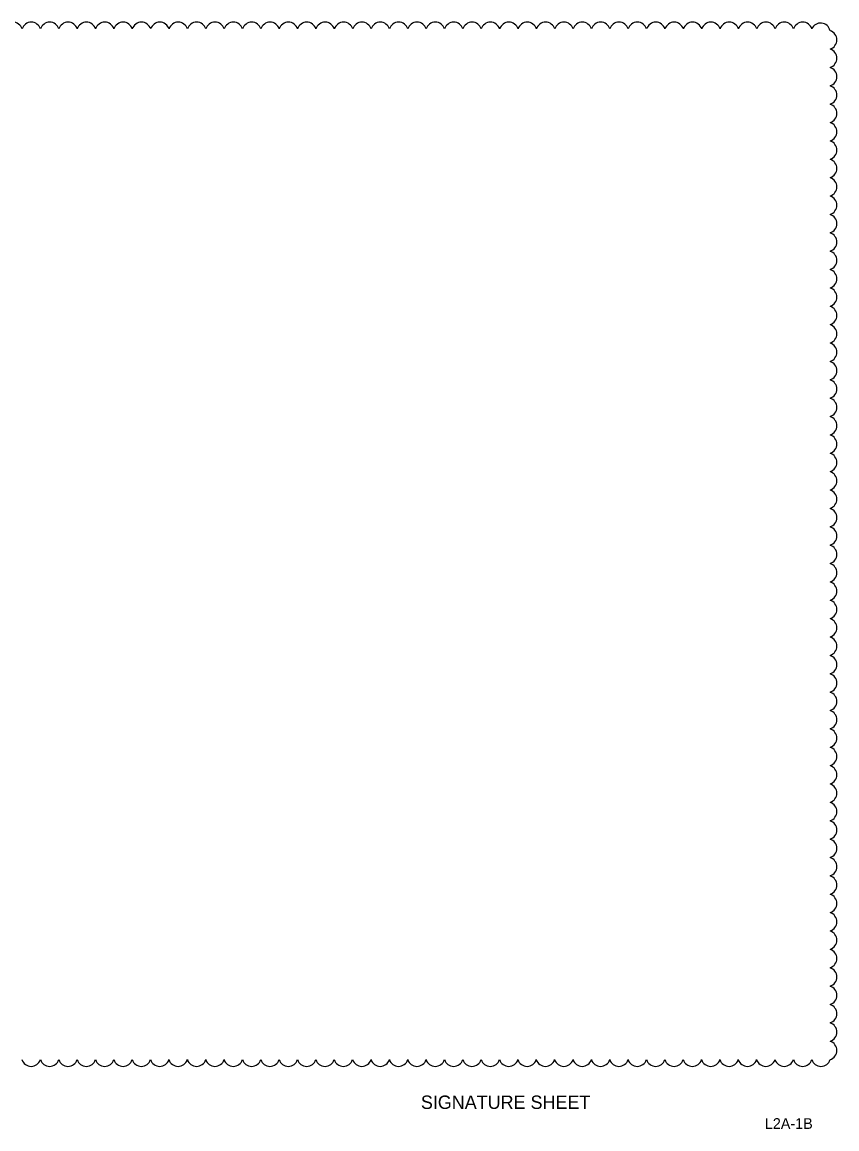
# Model space of a CAD drawing. Extents: x -811 to -790, y -2284 to -2178.
# Drawn here: x -802.91 to -795.32, y -2214.25 to -2203.94 of the extents above; entities that cross this region are included whole.
import ezdxf

# ---------------------------------------------------------------- set-up
doc = ezdxf.new("R2010")
doc.units = 0
for name, color, linetype in [('PlotBorder_dp', 7, 'Continuous'), ('SheetLines_dp', 7, 'Continuous'), ('TextTitle', 7, 'Continuous')]:
    doc.layers.add(name, color=color, linetype=linetype)

msp = doc.modelspace()

# ---------------------------------------------------------------- linework, layer by layer
at = {"layer": 'TextTitle'}
for centre, radius, start, end in [((-803, -2204.028), 0.0897, 17.5, 162.5), ((-802.829, -2204.028), 0.0897, 17.5, 162.5), ((-802.657, -2204.028), 0.0897, 17.5, 162.5), ((-802.486, -2204.028), 0.0897, 17.5, 162.5), ((-802.315, -2204.028), 0.0897, 17.5, 162.5), ((-802.144, -2204.028), 0.0897, 17.5, 162.5), ((-801.973, -2204.028), 0.0897, 17.5, 162.5), ((-801.802, -2204.028), 0.0897, 17.5, 162.5), ((-801.631, -2204.028), 0.0897, 17.5, 162.5), ((-801.46, -2204.028), 0.0897, 17.5, 162.5), ((-801.288, -2204.028), 0.0897, 17.5, 162.5), ((-801.117, -2204.028), 0.0897, 17.5, 162.5), ((-800.946, -2204.028), 0.0897, 17.5, 162.5), ((-800.775, -2204.028), 0.0897, 17.5, 162.5), ((-800.604, -2204.028), 0.0897, 17.5, 162.5), ((-800.433, -2204.028), 0.0897, 17.5, 162.5), ((-800.262, -2204.028), 0.0897, 17.5, 162.5), ((-800.091, -2204.028), 0.0897, 17.5, 162.5), ((-799.919, -2204.028), 0.0897, 17.5, 162.5), ((-799.748, -2204.028), 0.0897, 17.5, 162.5), ((-799.577, -2204.028), 0.0897, 17.5, 162.5), ((-799.406, -2204.028), 0.0897, 17.5, 162.5), ((-799.235, -2204.028), 0.0897, 17.5, 162.5), ((-799.064, -2204.028), 0.0897, 17.5, 162.5), ((-798.893, -2204.028), 0.0897, 17.5, 162.5), ((-798.722, -2204.028), 0.0897, 17.5, 162.5), ((-798.551, -2204.028), 0.0897, 17.5, 162.5), ((-798.379, -2204.028), 0.0897, 17.5, 162.5), ((-798.208, -2204.028), 0.0897, 17.5, 162.5), ((-798.037, -2204.028), 0.0897, 17.5, 162.5), ((-797.866, -2204.028), 0.0897, 17.5, 162.5), ((-797.695, -2204.028), 0.0897, 17.5, 162.5), ((-797.524, -2204.028), 0.0897, 17.5, 162.5), ((-797.353, -2204.028), 0.0897, 17.5, 162.5), ((-797.182, -2204.028), 0.0897, 17.5, 162.5), ((-797.01, -2204.028), 0.0897, 17.5, 162.5), ((-796.839, -2204.028), 0.0897, 17.5, 162.5), ((-796.668, -2204.028), 0.0897, 17.5, 162.5), ((-796.497, -2204.028), 0.0897, 17.5, 162.5), ((-796.326, -2204.028), 0.0897, 17.5, 162.5), ((-796.155, -2204.028), 0.0897, 17.5, 162.5), ((-795.984, -2204.028), 0.0897, 17.5, 162.5), ((-795.813, -2204.028), 0.0897, 17.5, 162.5), ((-795.641, -2204.028), 0.0897, 17.5, 162.5), ((-795.474, -2204.036), 0.0896, 11.7454, 156.7454), ((-795.413, -2204.103), 0.0897, 287.5, 72.5), ((-795.413, -2204.274), 0.0897, 287.5, 72.5), ((-795.413, -2204.446), 0.0897, 287.5, 72.5), ((-795.413, -2204.617), 0.0897, 287.5, 72.5), ((-795.413, -2204.788), 0.0897, 287.5, 72.5), ((-795.413, -2204.959), 0.0897, 287.5, 72.5), ((-795.413, -2205.13), 0.0897, 287.5, 72.5), ((-795.413, -2205.301), 0.0897, 287.5, 72.5), ((-795.413, -2205.472), 0.0897, 287.5, 72.5), ((-795.413, -2205.643), 0.0897, 287.5, 72.5), ((-795.413, -2205.815), 0.0897, 287.5, 72.5), ((-795.413, -2205.986), 0.0897, 287.5, 72.5), ((-795.413, -2206.157), 0.0897, 287.5, 72.5), ((-795.413, -2206.328), 0.0897, 287.5, 72.5), ((-795.413, -2206.499), 0.0897, 287.5, 72.5), ((-795.413, -2206.67), 0.0897, 287.5, 72.5), ((-795.413, -2206.841), 0.0897, 287.5, 72.5), ((-795.413, -2207.012), 0.0897, 287.5, 72.5), ((-795.413, -2207.184), 0.0897, 287.5, 72.5), ((-795.413, -2207.355), 0.0897, 287.5, 72.5), ((-795.413, -2207.526), 0.0897, 287.5, 72.5), ((-795.413, -2207.697), 0.0897, 287.5, 72.5), ((-795.413, -2207.868), 0.0897, 287.5, 72.5), ((-795.413, -2208.039), 0.0897, 287.5, 72.5), ((-795.413, -2208.21), 0.0897, 287.5, 72.5), ((-795.413, -2208.381), 0.0897, 287.5, 72.5), ((-795.413, -2208.553), 0.0897, 287.5, 72.5), ((-795.413, -2208.724), 0.0897, 287.5, 72.5), ((-795.413, -2208.895), 0.0897, 287.5, 72.5), ((-795.413, -2209.066), 0.0897, 287.5, 72.5), ((-795.413, -2209.237), 0.0897, 287.5, 72.5), ((-795.413, -2209.408), 0.0897, 287.5, 72.5), ((-795.413, -2209.579), 0.0897, 287.5, 72.5), ((-795.413, -2209.75), 0.0897, 287.5, 72.5), ((-795.413, -2209.922), 0.0897, 287.5, 72.5), ((-795.413, -2210.093), 0.0897, 287.5, 72.5), ((-795.413, -2210.264), 0.0897, 287.5, 72.5), ((-795.413, -2210.435), 0.0897, 287.5, 72.5), ((-795.413, -2210.606), 0.0897, 287.5, 72.5), ((-795.413, -2210.777), 0.0897, 287.5, 72.5), ((-795.413, -2210.948), 0.0897, 287.5, 72.5), ((-795.413, -2211.119), 0.0897, 287.5, 72.5), ((-795.413, -2211.29), 0.0897, 287.5, 72.5), ((-795.413, -2211.462), 0.0897, 287.5, 72.5), ((-795.413, -2211.633), 0.0897, 287.5, 72.5), ((-795.413, -2211.804), 0.0897, 287.5, 72.5), ((-795.413, -2211.975), 0.0897, 287.5, 72.5), ((-795.413, -2212.146), 0.0897, 287.5, 72.5), ((-795.413, -2212.317), 0.0897, 287.5, 72.5), ((-795.413, -2212.488), 0.0897, 287.5, 72.5), ((-795.413, -2212.659), 0.0897, 287.5, 72.5), ((-795.413, -2212.831), 0.0897, 287.5, 72.5), ((-795.413, -2213.002), 0.0897, 287.5, 72.5), ((-795.413, -2213.173), 0.0897, 287.5, 72.5), ((-795.413, -2213.344), 0.0897, 287.5, 72.5), ((-795.413, -2213.515), 0.0897, 287.5, 72.5), ((-802.83, -2213.574), 0.0897, 197.5, 342.5), ((-802.658, -2213.574), 0.0897, 197.5, 342.5), ((-802.487, -2213.574), 0.0897, 197.5, 342.5), ((-802.316, -2213.574), 0.0897, 197.5, 342.5), ((-802.145, -2213.574), 0.0897, 197.5, 342.5), ((-801.974, -2213.574), 0.0897, 197.5, 342.5), ((-801.803, -2213.574), 0.0897, 197.5, 342.5), ((-801.632, -2213.574), 0.0897, 197.5, 342.5), ((-801.461, -2213.574), 0.0897, 197.5, 342.5), ((-801.289, -2213.574), 0.0897, 197.5, 342.5), ((-801.118, -2213.574), 0.0897, 197.5, 342.5), ((-800.947, -2213.574), 0.0897, 197.5, 342.5), ((-800.776, -2213.574), 0.0897, 197.5, 342.5), ((-800.605, -2213.574), 0.0897, 197.5, 342.5), ((-800.434, -2213.574), 0.0897, 197.5, 342.5), ((-800.263, -2213.574), 0.0897, 197.5, 342.5), ((-800.092, -2213.574), 0.0897, 197.5, 342.5), ((-799.921, -2213.574), 0.0897, 197.5, 342.5), ((-799.749, -2213.574), 0.0897, 197.5, 342.5), ((-799.578, -2213.574), 0.0897, 197.5, 342.5), ((-799.407, -2213.574), 0.0897, 197.5, 342.5), ((-799.236, -2213.574), 0.0897, 197.5, 342.5), ((-799.065, -2213.574), 0.0897, 197.5, 342.5), ((-798.894, -2213.574), 0.0897, 197.5, 342.5), ((-798.723, -2213.574), 0.0897, 197.5, 342.5), ((-798.552, -2213.574), 0.0897, 197.5, 342.5), ((-798.38, -2213.574), 0.0897, 197.5, 342.5), ((-798.209, -2213.574), 0.0897, 197.5, 342.5), ((-798.038, -2213.574), 0.0897, 197.5, 342.5), ((-797.867, -2213.574), 0.0897, 197.5, 342.5), ((-797.696, -2213.574), 0.0897, 197.5, 342.5), ((-797.525, -2213.574), 0.0897, 197.5, 342.5), ((-797.354, -2213.574), 0.0897, 197.5, 342.5), ((-797.183, -2213.574), 0.0897, 197.5, 342.5), ((-797.011, -2213.574), 0.0897, 197.5, 342.5), ((-796.84, -2213.574), 0.0897, 197.5, 342.5), ((-796.669, -2213.574), 0.0897, 197.5, 342.5), ((-796.498, -2213.574), 0.0897, 197.5, 342.5), ((-796.327, -2213.574), 0.0897, 197.5, 342.5), ((-796.156, -2213.574), 0.0897, 197.5, 342.5), ((-795.985, -2213.574), 0.0897, 197.5, 342.5), ((-795.814, -2213.574), 0.0897, 197.5, 342.5), ((-795.642, -2213.574), 0.0897, 197.5, 342.5), ((-795.471, -2213.574), 0.0897, 197.5, 342.5)]:
    msp.add_arc(centre, radius, start, end, dxfattribs=at)

# ---------------------------------------------------------------- texts
at = {"layer": 'PlotBorder_dp'}
msp.add_text('       SIGNATURE SHEET         ', height=0.125, dxfattribs=at).set_placement((-799.524, -2214.06))
at = {"layer": 'SheetLines_dp'}
msp.add_text('L2A-1B', height=0.1, dxfattribs=at).set_placement((-795.994, -2214.246))

doc.saveas('drawing.dxf')
